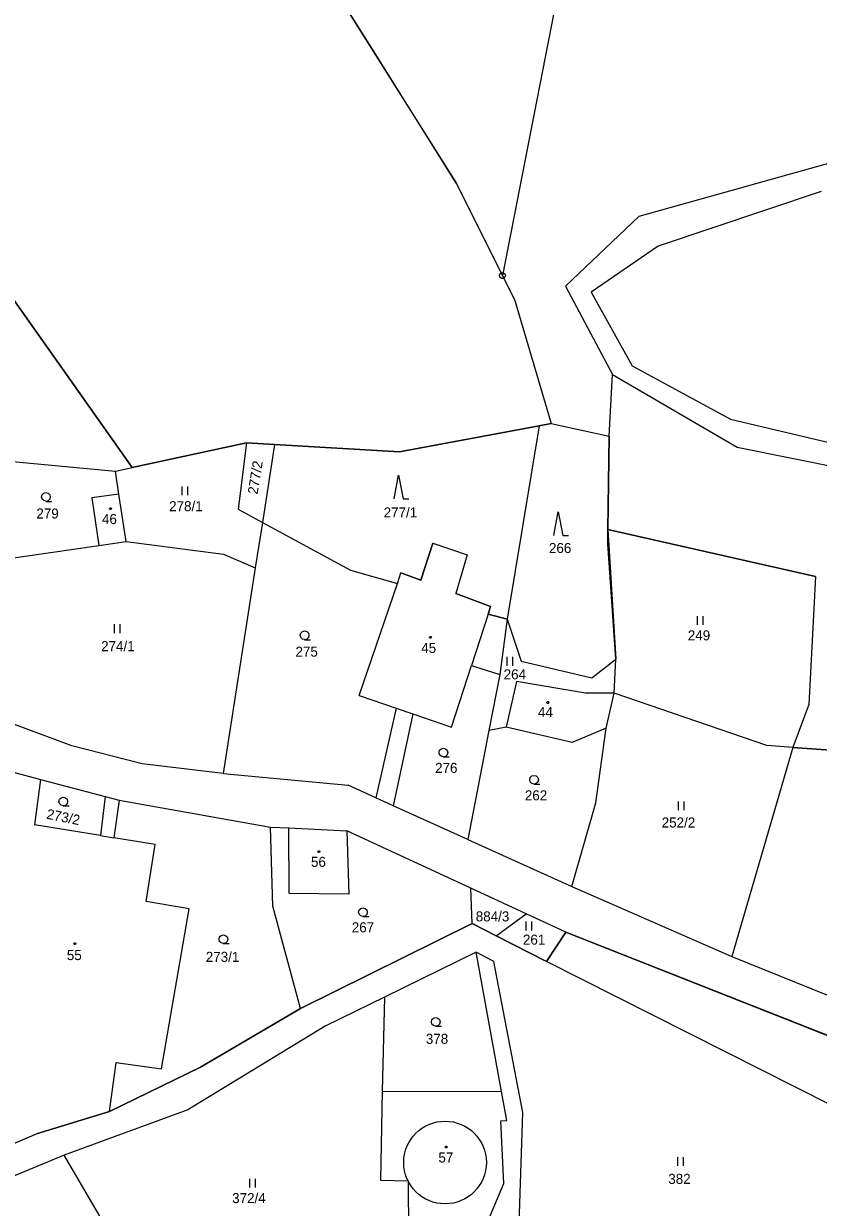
# Model space of a CAD drawing. Extents: x -580551 to -575069, y -1073031 to -1067931.
# Drawn here: x -577203.9 to -577069.2, y -1069968.7 to -1069768.1 of the extents above; entities that cross this region are included whole.
import ezdxf

# ---------------------------------------------------------------- set-up
doc = ezdxf.new("R2010")
doc.units = 0
for name, color, linetype in [('Druh pozemku', 7, 'Continuous'), ('Geodetické body', 7, 'Continuous'), ('Hranice z DKM', 7, 'Continuous'), ('Parcela', 7, 'Continuous'), ('Parcelní číslo', 7, 'Continuous'), ('Parcelní číslo_stavba', 7, 'Continuous'), ('SR - hranice státu', 7, 'Continuous'), ('stavební parcely', 7, 'Continuous'), ('Vnitřní kresba', 7, 'Continuous')]:
    doc.layers.add(name, color=color, linetype=linetype)

msp = doc.modelspace()

# ---------------------------------------------------------------- linework, layer by layer
at = {"layer": 'Druh pozemku'}
for p, q in [((-577177.07, -1069846.55), (-577177.07, -1069848.05)), ((-577176.07, -1069848.05), (-577176.07, -1069846.55)), ((-577089.73, -1069868.51), (-577089.73, -1069870.01)), ((-577088.73, -1069870.01), (-577088.73, -1069868.51)), ((-577188.54, -1069869.92), (-577188.54, -1069871.42)), ((-577187.54, -1069871.42), (-577187.54, -1069869.92)), ((-577121.99, -1069875.43), (-577121.99, -1069876.93)), ((-577120.99, -1069876.93), (-577120.99, -1069875.43)), ((-577092.97, -1069899.92), (-577092.97, -1069901.42)), ((-577091.97, -1069901.42), (-577091.97, -1069899.92)), ((-577118.75, -1069920.29), (-577118.75, -1069921.79)), ((-577117.75, -1069921.79), (-577117.75, -1069920.29)), ((-577093.08, -1069960.19), (-577093.08, -1069961.69)), ((-577092.08, -1069961.69), (-577092.08, -1069960.19)), ((-577165.6, -1069963.87), (-577165.6, -1069965.37)), ((-577164.6, -1069965.37), (-577164.6, -1069963.87))]:
    msp.add_line(p, q, dxfattribs=at)
for points in [[(-577141.09, -1069848.64), (-577140.34, -1069844.64), (-577139.59, -1069848.64), (-577138.59, -1069848.64)], [(-577200.09, -1069849.06), (-577200.47, -1069848.96), (-577200.74, -1069848.69), (-577200.84, -1069848.32), (-577200.74, -1069847.95), (-577200.47, -1069847.68), (-577200.1, -1069847.58), (-577199.73, -1069847.68), (-577199.46, -1069847.95), (-577199.36, -1069848.33), (-577199.46, -1069848.71), (-577199.73, -1069848.98), (-577200.11, -1069849.08), (-577199.11, -1069849.08)], [(-577114.03, -1069854.84), (-577113.28, -1069850.84), (-577112.53, -1069854.84), (-577111.53, -1069854.84)], [(-577156.26, -1069872.51), (-577156.64, -1069872.41), (-577156.91, -1069872.14), (-577157.01, -1069871.77), (-577156.91, -1069871.4), (-577156.64, -1069871.13), (-577156.27, -1069871.03), (-577155.9, -1069871.13), (-577155.63, -1069871.4), (-577155.53, -1069871.78), (-577155.63, -1069872.16), (-577155.9, -1069872.43), (-577156.28, -1069872.53), (-577155.28, -1069872.53)], [(-577132.73, -1069892.38), (-577133.11, -1069892.28), (-577133.38, -1069892.01), (-577133.48, -1069891.64), (-577133.38, -1069891.27), (-577133.11, -1069891), (-577132.74, -1069890.9), (-577132.37, -1069891), (-577132.1, -1069891.27), (-577132, -1069891.65), (-577132.1, -1069892.03), (-577132.37, -1069892.3), (-577132.75, -1069892.4), (-577131.75, -1069892.4)], [(-577117.37, -1069897), (-577117.75, -1069896.9), (-577118.02, -1069896.63), (-577118.12, -1069896.26), (-577118.02, -1069895.89), (-577117.75, -1069895.62), (-577117.38, -1069895.52), (-577117.01, -1069895.62), (-577116.74, -1069895.89), (-577116.64, -1069896.27), (-577116.74, -1069896.65), (-577117.01, -1069896.92), (-577117.39, -1069897.02), (-577116.39, -1069897.02)], [(-577197.15, -1069900.68), (-577197.53, -1069900.58), (-577197.8, -1069900.31), (-577197.9, -1069899.94), (-577197.8, -1069899.57), (-577197.53, -1069899.3), (-577197.16, -1069899.2), (-577196.79, -1069899.3), (-577196.52, -1069899.57), (-577196.42, -1069899.95), (-577196.52, -1069900.33), (-577196.79, -1069900.6), (-577197.17, -1069900.7), (-577196.17, -1069900.7)], [(-577146.37, -1069919.43), (-577146.75, -1069919.33), (-577147.02, -1069919.06), (-577147.12, -1069918.69), (-577147.02, -1069918.32), (-577146.75, -1069918.05), (-577146.38, -1069917.95), (-577146.01, -1069918.05), (-577145.74, -1069918.32), (-577145.64, -1069918.7), (-577145.74, -1069919.08), (-577146.01, -1069919.35), (-577146.39, -1069919.45), (-577145.39, -1069919.45)], [(-577170.02, -1069924.01), (-577170.4, -1069923.91), (-577170.67, -1069923.64), (-577170.77, -1069923.27), (-577170.67, -1069922.9), (-577170.4, -1069922.63), (-577170.03, -1069922.53), (-577169.66, -1069922.63), (-577169.39, -1069922.9), (-577169.29, -1069923.28), (-577169.39, -1069923.66), (-577169.66, -1069923.93), (-577170.04, -1069924.03), (-577169.04, -1069924.03)], [(-577134.04, -1069938.02), (-577134.42, -1069937.92), (-577134.69, -1069937.65), (-577134.79, -1069937.28), (-577134.69, -1069936.91), (-577134.42, -1069936.64), (-577134.05, -1069936.54), (-577133.68, -1069936.64), (-577133.41, -1069936.91), (-577133.31, -1069937.29), (-577133.41, -1069937.67), (-577133.68, -1069937.94), (-577134.06, -1069938.04), (-577133.06, -1069938.04)]]:
    msp.add_lwpolyline(points, dxfattribs=at)
for points in [[(-577189.07, -1069850.19), (-577188.98, -1069850.34), (-577189.07, -1069850.49), (-577189.25, -1069850.49), (-577189.34, -1069850.34), (-577189.25, -1069850.19)], [(-577134.85, -1069871.98), (-577134.76, -1069872.13), (-577134.85, -1069872.28), (-577135.03, -1069872.28), (-577135.12, -1069872.13), (-577135.03, -1069871.98)], [(-577114.97, -1069883.01), (-577114.88, -1069883.16), (-577114.97, -1069883.31), (-577115.15, -1069883.31), (-577115.24, -1069883.16), (-577115.15, -1069883.01)], [(-577153.75, -1069908.29), (-577153.66, -1069908.44), (-577153.75, -1069908.59), (-577153.93, -1069908.59), (-577154.02, -1069908.44), (-577153.93, -1069908.29)], [(-577195.12, -1069923.88), (-577195.03, -1069924.03), (-577195.12, -1069924.18), (-577195.3, -1069924.18), (-577195.39, -1069924.03), (-577195.3, -1069923.88)], [(-577132.17, -1069958.34), (-577132.08, -1069958.49), (-577132.17, -1069958.64), (-577132.35, -1069958.64), (-577132.44, -1069958.49), (-577132.35, -1069958.34)]]:
    msp.add_lwpolyline(points, close=True, dxfattribs=at)
at = {"layer": 'Geodetické body'}
msp.add_line((-577122.87, -1069810.83), (-577122.63, -1069810.83), dxfattribs=at)
msp.add_lwpolyline([(-577122.6, -1069810.35), (-577122.35, -1069810.53), (-577122.25, -1069810.82), (-577122.35, -1069811.11), (-577122.6, -1069811.29), (-577122.91, -1069811.29), (-577123.16, -1069811.11), (-577123.26, -1069810.82), (-577123.16, -1069810.53), (-577122.91, -1069810.35)], close=True, dxfattribs=at)
at = {"layer": 'Hranice z DKM'}
msp.add_line((-577104.64, -1069838.02), (-577104.87, -1069853.83), dxfattribs=at)
for points in [[(-577177.26, -1069685.44), (-577170.48, -1069724.14), (-577162.31, -1069744.73), (-577130.52, -1069795.24), (-577122.75, -1069810.83)], [(-577122.75, -1069810.83), (-577120.62, -1069815.02), (-577114.5, -1069835.87)], [(-577161.37, -1069839.45), (-577140.18, -1069840.71), (-577116.53, -1069836.27), (-577121.95, -1069869.07)], [(-577116.53, -1069836.27), (-577114.5, -1069835.87), (-577104.64, -1069838.02)]]:
    msp.add_lwpolyline(points, dxfattribs=at)
at = {"layer": 'Parcela'}
for p, q in [((-577097.24, -1069680.48), (-577122.75, -1069810.83)), ((-577144.86, -1069772.29), (-577162.31, -1069744.73)), ((-577130.52, -1069795.24), (-577144.86, -1069772.29)), ((-577065.27, -1069791.23), (-577099.61, -1069800.79)), ((-577122.75, -1069810.83), (-577130.52, -1069795.24)), ((-577068.75, -1069796.56), (-577096.37, -1069805.82)), ((-577099.61, -1069800.79), (-577112.04, -1069812.59)), ((-577096.37, -1069805.82), (-577107.71, -1069813.61)), ((-577122.75, -1069810.83), (-577120.62, -1069815.02)), ((-577112.04, -1069812.59), (-577104.07, -1069827.56)), ((-577107.71, -1069813.61), (-577100.76, -1069826.13)), ((-577185.48, -1069843.33), (-577205.71, -1069814.7)), ((-577120.62, -1069815.02), (-577114.5, -1069835.87)), ((-577104.64, -1069838.02), (-577104.07, -1069827.56)), ((-577104.07, -1069827.56), (-577082.96, -1069839.91)), ((-577100.76, -1069826.13), (-577084.11, -1069835.17)), ((-577084.11, -1069835.17), (-577065.48, -1069839.55)), ((-577116.53, -1069836.27), (-577140.18, -1069840.71)), ((-577116.53, -1069836.27), (-577121.95, -1069869.07)), ((-577114.5, -1069835.87), (-577116.53, -1069836.27)), ((-577114.5, -1069835.87), (-577104.64, -1069838.02)), ((-577166.12, -1069839.17), (-577185.48, -1069843.33)), ((-577166.12, -1069839.17), (-577167.54, -1069850.41)), ((-577161.37, -1069839.45), (-577166.12, -1069839.17)), ((-577161.37, -1069839.45), (-577163.43, -1069852.64)), ((-577140.18, -1069840.71), (-577161.37, -1069839.45)), ((-577104.87, -1069853.83), (-577104.64, -1069838.02)), ((-577082.96, -1069839.91), (-577064.57, -1069843.63)), ((-577207.6, -1069842.17), (-577188.34, -1069843.99)), ((-577188.34, -1069843.99), (-577185.48, -1069843.33)), ((-577187.75, -1069847.86), (-577188.34, -1069843.99)), ((-577187.75, -1069847.86), (-577192.35, -1069848.5)), ((-577192.35, -1069848.5), (-577191.14, -1069856.54)), ((-577186.52, -1069855.87), (-577187.75, -1069847.86)), ((-577167.54, -1069850.41), (-577163.43, -1069852.64)), ((-577163.43, -1069852.64), (-577164.63, -1069860.34)), ((-577163.43, -1069852.64), (-577148.51, -1069860.72)), ((-577104.9, -1069856.28), (-577104.87, -1069853.83)), ((-577104.87, -1069853.83), (-577069.67, -1069861.8)), ((-577208.88, -1069859.13), (-577191.14, -1069856.54)), ((-577191.14, -1069856.54), (-577186.52, -1069855.87)), ((-577186.52, -1069855.87), (-577170, -1069858.01)), ((-577134.54, -1069856.15), (-577136.58, -1069862.44)), ((-577134.54, -1069856.15), (-577128.74, -1069858.14)), ((-577103.54, -1069875.83), (-577104.9, -1069856.28)), ((-577170, -1069858.01), (-577164.63, -1069860.34)), ((-577128.74, -1069858.14), (-577130.66, -1069864.68)), ((-577164.63, -1069860.34), (-577170.06, -1069895.18)), ((-577148.51, -1069860.72), (-577140.55, -1069862.99)), ((-577140.55, -1069862.99), (-577139.94, -1069861.18)), ((-577136.58, -1069862.44), (-577139.94, -1069861.18)), ((-577069.67, -1069861.8), (-577070.84, -1069883.52)), ((-577147.03, -1069882), (-577140.55, -1069862.99)), ((-577124.74, -1069866.91), (-577130.66, -1069864.68)), ((-577125.16, -1069868.21), (-577124.74, -1069866.91)), ((-577121.95, -1069869.07), (-577125.16, -1069868.21)), ((-577121.95, -1069869.07), (-577123.19, -1069878.45)), ((-577121.95, -1069869.07), (-577119.57, -1069876.14)), ((-577107.61, -1069879.01), (-577103.54, -1069875.83)), ((-577103.82, -1069881.56), (-577103.54, -1069875.83)), ((-577131.37, -1069887.32), (-577127.98, -1069876.89)), ((-577127.98, -1069876.89), (-577123.19, -1069878.45)), ((-577119.57, -1069876.14), (-577107.61, -1069879.01)), ((-577123.19, -1069878.45), (-577125.06, -1069887.93)), ((-577120.34, -1069879.59), (-577122.09, -1069887.36)), ((-577108.66, -1069881.61), (-577120.34, -1069879.59)), ((-577103.82, -1069881.56), (-577108.66, -1069881.61)), ((-577105.19, -1069887.52), (-577103.82, -1069881.56)), ((-577077.91, -1069890.48), (-577103.82, -1069881.56)), ((-577147.03, -1069882), (-577140.73, -1069884.14)), ((-577070.84, -1069883.52), (-577073.55, -1069890.78)), ((-577195.72, -1069890.5), (-577210.81, -1069884.91)), ((-577140.73, -1069884.14), (-577144.19, -1069899.33)), ((-577137.94, -1069885.09), (-577141.27, -1069900.65)), ((-577137.94, -1069885.09), (-577131.37, -1069887.32)), ((-577122.09, -1069887.36), (-577125.06, -1069887.93)), ((-577110.9, -1069889.93), (-577122.09, -1069887.36)), ((-577105.19, -1069887.52), (-577110.9, -1069889.93)), ((-577106.93, -1069900.19), (-577105.19, -1069887.52)), ((-577125.06, -1069887.93), (-577128.58, -1069906.38)), ((-577183.78, -1069893.54), (-577195.72, -1069890.5)), ((-577073.55, -1069890.78), (-577083.84, -1069926.22)), ((-577073.55, -1069890.78), (-577077.91, -1069890.48)), ((-577053.57, -1069892.18), (-577073.55, -1069890.78)), ((-577170.06, -1069895.18), (-577183.78, -1069893.54)), ((-577209.21, -1069894.03), (-577201.02, -1069896.19)), ((-577170.06, -1069895.18), (-577148.89, -1069897.2)), ((-577201.02, -1069896.19), (-577202.04, -1069903.87)), ((-577201.02, -1069896.19), (-577190.06, -1069899.09)), ((-577144.19, -1069899.33), (-577148.89, -1069897.2)), ((-577190.06, -1069899.09), (-577190.88, -1069905.71)), ((-577190.06, -1069899.09), (-577187.67, -1069899.72)), ((-577187.67, -1069899.72), (-577188.57, -1069906.09)), ((-577187.67, -1069899.72), (-577162.07, -1069904.27)), ((-577141.27, -1069900.65), (-577144.19, -1069899.33)), ((-577128.58, -1069906.38), (-577141.27, -1069900.65)), ((-577110.97, -1069914.34), (-577106.93, -1069900.19)), ((-577190.88, -1069905.71), (-577202.04, -1069903.87)), ((-577161.66, -1069917.69), (-577162.07, -1069904.27)), ((-577162.07, -1069904.27), (-577158.96, -1069904.43)), ((-577158.96, -1069904.43), (-577149.09, -1069904.94)), ((-577158.89, -1069915.55), (-577158.96, -1069904.43)), ((-577128.11, -1069914.62), (-577149.09, -1069904.94)), ((-577149.09, -1069904.94), (-577148.75, -1069915.65)), ((-577181.58, -1069907.24), (-577188.57, -1069906.09)), ((-577183.09, -1069916.91), (-577181.58, -1069907.24)), ((-577128.58, -1069906.38), (-577110.97, -1069914.34)), ((-577148.75, -1069915.65), (-577158.89, -1069915.55)), ((-577127.87, -1069920.6), (-577128.11, -1069914.62)), ((-577118.73, -1069918.98), (-577128.11, -1069914.62)), ((-577110.97, -1069914.34), (-577083.84, -1069926.22)), ((-577175.85, -1069918.13), (-577183.09, -1069916.91)), ((-577156.97, -1069935), (-577161.66, -1069917.69)), ((-577180.52, -1069945.27), (-577175.85, -1069918.13)), ((-577123.8, -1069922.68), (-577118.73, -1069918.98)), ((-577112.01, -1069922.1), (-577118.73, -1069918.98)), ((-577127.87, -1069920.6), (-577156.97, -1069935)), ((-577123.8, -1069922.68), (-577127.87, -1069920.6)), ((-577115.27, -1069927.04), (-577123.8, -1069922.68)), ((-577112.01, -1069922.1), (-577115.27, -1069927.04)), ((-577050.1, -1069946.52), (-577112.01, -1069922.1)), ((-577127.2, -1069925.49), (-577142.75, -1069933.1)), ((-577124.19, -1069927.05), (-577127.2, -1069925.49)), ((-577122.91, -1069949.1), (-577127.2, -1069925.49)), ((-577119.29, -1069952.63), (-577124.19, -1069927.05)), ((-577067.04, -1069951.41), (-577115.27, -1069927.04)), ((-577083.84, -1069926.22), (-577050.94, -1069939.56)), ((-577142.75, -1069933.1), (-577152.8, -1069938.02)), ((-577142.75, -1069933.1), (-577143.1, -1069949.01)), ((-577156.97, -1069935), (-577173.9, -1069944.95)), ((-577152.8, -1069938.02), (-577176.03, -1069952.19)), ((-577189.32, -1069952.46), (-577188.18, -1069944.16)), ((-577173.9, -1069944.95), (-577189.32, -1069952.46)), ((-577188.18, -1069944.16), (-577180.52, -1069945.27)), ((-577143.1, -1069949.01), (-577143.43, -1069964.11)), ((-577143.1, -1069949.01), (-577122.91, -1069949.1)), ((-577122.02, -1069953.98), (-577122.91, -1069949.1)), ((-577189.32, -1069952.46), (-577201.68, -1069956.25)), ((-577176.03, -1069952.19), (-577197.02, -1069959.85)), ((-577123.02, -1069954.04), (-577122.02, -1069953.98)), ((-577122.48, -1069964.7), (-577123.02, -1069954.04)), ((-577119.95, -1069973.43), (-577119.29, -1069952.63)), ((-577218.87, -1069963.52), (-577201.68, -1069956.25)), ((-577197.02, -1069959.85), (-577219.63, -1069969.3)), ((-577174.37, -1069998.46), (-577197.02, -1069959.85)), ((-577143.43, -1069964.11), (-577138.74, -1069964.25)), ((-577138.74, -1069964.25), (-577138.66, -1069975.52)), ((-577125.46, -1069971.6), (-577122.48, -1069964.7))]:
    msp.add_line(p, q, dxfattribs=at)
at = {"layer": 'SR - hranice státu'}
for p, q in [((-577069.67, -1069861.8), (-577104.87, -1069853.83)), ((-577104.87, -1069853.83), (-577103.54, -1069875.83)), ((-577073.55, -1069890.78), (-577053.57, -1069892.18))]:
    msp.add_line(p, q, dxfattribs=at)
for points in [[(-577220.08, -1069791.36), (-577218.58, -1069811.4), (-577205.71, -1069814.7), (-577185.48, -1069843.33)], [(-577185.48, -1069843.33), (-577166.12, -1069839.17), (-577161.37, -1069839.45)], [(-577161.37, -1069839.45), (-577163.43, -1069852.64), (-577148.51, -1069860.72), (-577140.55, -1069862.99), (-577139.94, -1069861.18), (-577136.58, -1069862.44), (-577134.54, -1069856.15), (-577128.74, -1069858.14), (-577130.66, -1069864.68), (-577124.74, -1069866.91), (-577125.16, -1069868.21), (-577121.95, -1069869.07), (-577119.57, -1069876.14)], [(-577069.67, -1069861.8), (-577070.84, -1069883.52), (-577073.55, -1069890.78)], [(-577119.57, -1069876.14), (-577107.61, -1069879.01), (-577103.54, -1069875.83)], [(-577223.71, -1069965.71), (-577218.87, -1069963.52), (-577201.68, -1069956.25), (-577189.32, -1069952.46), (-577173.9, -1069944.95), (-577156.97, -1069935), (-577127.87, -1069920.6), (-577123.8, -1069922.68)], [(-577123.8, -1069922.68), (-577115.27, -1069927.04), (-577112.01, -1069922.1)], [(-577112.01, -1069922.1), (-577050.1, -1069946.52), (-577029.68, -1069945.77), (-577003.65, -1069941.21), (-577000.48, -1069940.66)]]:
    msp.add_lwpolyline(points, dxfattribs=at)
at = {"layer": 'stavební parcely'}
msp.add_circle((-577132.47, -1069961.12), 7.008, dxfattribs=at)
at = {"layer": 'Vnitřní kresba'}
for p, q in [((-577125.16, -1069868.21), (-577127.98, -1069876.89)), ((-577140.73, -1069884.14), (-577137.94, -1069885.09)), ((-577190.88, -1069905.71), (-577188.57, -1069906.09))]:
    msp.add_line(p, q, dxfattribs=at)

# ---------------------------------------------------------------- texts
at = {"layer": 'Parcelní číslo'}
for s, rotation, p in [('277/2', 80.84434, (-577164.251, -1069847.979)), ('273/2', 348.64482, (-577200.108, -1069902.84))]:
    msp.add_text(s, height=1.7, rotation=rotation, dxfattribs=at).set_placement(p)
for s, p in [('278/1', (-577179.225, -1069850.75)), ('279', (-577201.724, -1069851.99)), ('277/1', (-577142.876, -1069851.81)), ('266', (-577114.859, -1069857.84)), ('249', (-577091.329, -1069872.64)), ('274/1', (-577190.752, -1069874.47)), ('275', (-577157.815, -1069875.4)), ('264', (-577122.539, -1069879.25)), ('276', (-577134.154, -1069895.1)), ('262', (-577118.944, -1069899.75)), ('252/2', (-577095.756, -1069904.35)), ('884/3', (-577127.263, -1069920.26)), ('267', (-577148.274, -1069922.11)), ('261', (-577119.272, -1069924.2)), ('273/1', (-577173.019, -1069927.12)), ('378', (-577135.723, -1069941.01)), ('382', (-577094.64, -1069964.74)), ('372/4', (-577168.546, -1069968))]:
    msp.add_text(s, height=1.7, dxfattribs=at).set_placement(p)
at = {"layer": 'Parcelní číslo_stavba'}
for s, p in [('46', (-577190.606, -1069852.93)), ('45', (-577136.497, -1069874.77)), ('44', (-577116.716, -1069885.65)), ('56', (-577155.187, -1069911.02)), ('55', (-577196.559, -1069926.82)), ('57', (-577133.592, -1069961.12))]:
    msp.add_text(s, height=1.7, dxfattribs=at).set_placement(p)

doc.saveas('drawing.dxf')
